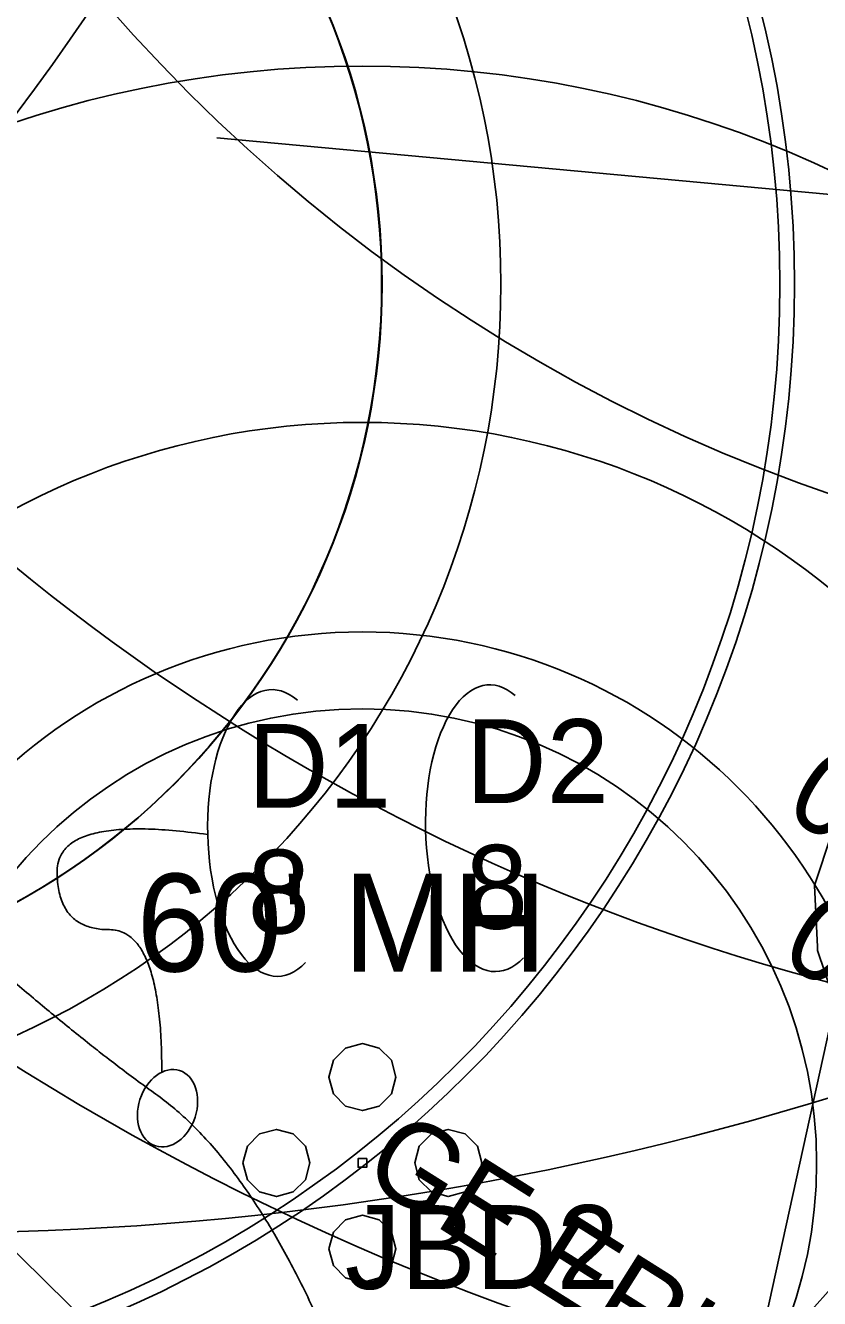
# Model space of a CAD drawing. Extents: x 1638506 to 1658005, y 834807 to 846788.
# Drawn here: x 1641345.7 to 1641459.3, y 842127.5 to 842309.7 of the extents above; entities that cross this region are included whole.
import ezdxf

# ---------------------------------------------------------------- set-up
doc = ezdxf.new("R2010")
doc.units = 0
for name, color, linetype in [('Default', 7, 'Continuous'), ('Old_Level_1', 7, 'Continuous'), ('Old_Level_2', 7, 'Continuous'), ('Old_Level_4', 7, 'Continuous'), ('Scratch_Level_0', 7, 'Continuous'), ('Sheet North Arrow CELL', 7, 'Continuous')]:
    doc.layers.add(name, color=color, linetype=linetype)

msp = doc.modelspace()

# ---------------------------------------------------------------- linework, layer by layer
at = {"layer": 'Default'}
msp.add_line((1641192.01, 842284.15), (1641394.9, 842084.34), dxfattribs=at)
for centre, start_param, end_param in [((1641412.54, 842194.83), 5.884886, 7.853982), ((1641381.36, 842194.15), 5.884886, 7.853982), ((1641412.54, 842194.83), 1.570796, 3.572354), ((1641381.36, 842194.15), 1.570796, 3.572354)]:
    msp.add_ellipse(centre, major_axis=(-0.49, 20.52), ratio=0.466223, start_param=start_param, end_param=end_param, dxfattribs=at)
msp.add_ellipse((1641366.05, 842154.75), major_axis=(-1.72, -5.4), ratio=0.730797, dxfattribs=at)
for points in [[(1641295.68, 842243.6), (1641303.97, 842209.15), (1641349.49, 842167.37), (1641379.28, 842146.14), (1641391.33, 842115.76)], [(1641365.23, 842159.91), (1641365.23, 842180.31), (1641350.25, 842180.31), (1641350.25, 842196.94), (1641371.79, 842193.93)]]:
    msp.add_open_spline(points, degree=2, dxfattribs=at)
at = {"layer": 'Old_Level_1'}
for radius in [365, 307, 240, 158, 101]:
    msp.add_circle((1641295.68, 842272.71), radius, dxfattribs=at)
at = {"layer": 'Old_Level_2'}
msp.add_line((1641373.11, 842293.63), (1642246.71, 842213.27), dxfattribs=at)
msp.add_arc((1641332.1, 842574.94), 438, 252.1948, 287.7872, dxfattribs=at)
at = {"layer": 'Old_Level_4'}
for points in [[(1641389.77, 842156.82), (1641391.52, 842155.06), (1641393.92, 842154.42), (1641396.32, 842155.06), (1641398.08, 842156.82), (1641398.72, 842159.22), (1641398.08, 842161.61), (1641396.32, 842163.37), (1641393.92, 842164.01), (1641391.52, 842163.37), (1641389.77, 842161.61), (1641389.12, 842159.22)], [(1641389.77, 842156.82), (1641391.52, 842155.06), (1641393.92, 842154.42), (1641396.32, 842155.06), (1641398.08, 842156.82), (1641398.72, 842159.22), (1641398.08, 842161.61), (1641396.32, 842163.37), (1641393.92, 842164.01), (1641391.52, 842163.37), (1641389.77, 842161.61), (1641389.12, 842159.22)], [(1641393.92, 842164.01), (1641391.52, 842163.37), (1641391.52, 842163.37)], [(1641396.32, 842163.37), (1641393.92, 842164.01), (1641393.92, 842164.01)], [(1641389.77, 842161.61), (1641389.12, 842159.22), (1641389.12, 842159.22)], [(1641391.52, 842163.37), (1641389.77, 842161.61), (1641389.77, 842161.61)], [(1641398.08, 842161.61), (1641396.32, 842163.37), (1641396.32, 842163.37)], [(1641398.72, 842159.22), (1641398.08, 842161.61), (1641398.08, 842161.61)], [(1641389.12, 842159.22), (1641389.77, 842156.82), (1641389.77, 842156.82)], [(1641398.08, 842156.82), (1641398.72, 842159.22), (1641398.72, 842159.22)], [(1641389.77, 842156.82), (1641391.52, 842155.06), (1641391.52, 842155.06)], [(1641396.32, 842155.06), (1641398.08, 842156.82), (1641398.08, 842156.82)], [(1641391.52, 842155.06), (1641393.92, 842154.42), (1641393.92, 842154.42)], [(1641393.92, 842154.42), (1641396.32, 842155.06), (1641396.32, 842155.06)], [(1641384.02, 842142.76), (1641385.78, 842144.51), (1641386.42, 842146.92), (1641385.78, 842149.32), (1641384.02, 842151.07), (1641381.62, 842151.72), (1641379.22, 842151.07), (1641377.47, 842149.32), (1641376.82, 842146.92), (1641377.47, 842144.51), (1641379.22, 842142.76), (1641381.62, 842142.11)], [(1641384.02, 842142.76), (1641385.78, 842144.51), (1641386.42, 842146.92), (1641385.78, 842149.32), (1641384.02, 842151.07), (1641381.62, 842151.72), (1641379.22, 842151.07), (1641377.47, 842149.32), (1641376.82, 842146.92), (1641377.47, 842144.51), (1641379.22, 842142.76), (1641381.62, 842142.11)], [(1641379.22, 842151.07), (1641377.47, 842149.32), (1641377.47, 842149.32)], [(1641381.62, 842151.72), (1641379.22, 842151.07), (1641379.22, 842151.07)], [(1641384.02, 842151.07), (1641381.62, 842151.72), (1641381.62, 842151.72)], [(1641385.78, 842149.32), (1641384.02, 842151.07), (1641384.02, 842151.07)], [(1641403.82, 842151.07), (1641402.07, 842149.32), (1641401.42, 842146.92), (1641402.07, 842144.51), (1641403.82, 842142.76), (1641406.22, 842142.11), (1641408.62, 842142.76), (1641410.38, 842144.51), (1641411.02, 842146.92), (1641410.38, 842149.32), (1641408.62, 842151.07), (1641406.22, 842151.72)], [(1641403.82, 842151.07), (1641402.07, 842149.32), (1641401.42, 842146.92), (1641402.07, 842144.51), (1641403.82, 842142.76), (1641406.22, 842142.11), (1641408.62, 842142.76), (1641410.38, 842144.51), (1641411.02, 842146.92), (1641410.38, 842149.32), (1641408.62, 842151.07), (1641406.22, 842151.72)], [(1641403.82, 842151.07), (1641402.07, 842149.32), (1641402.07, 842149.32)], [(1641406.22, 842151.72), (1641403.82, 842151.07), (1641403.82, 842151.07)], [(1641408.62, 842151.07), (1641406.22, 842151.72), (1641406.22, 842151.72)], [(1641410.38, 842149.32), (1641408.62, 842151.07), (1641408.62, 842151.07)], [(1641377.47, 842149.32), (1641376.82, 842146.92), (1641376.82, 842146.92)], [(1641386.42, 842146.92), (1641385.78, 842149.32), (1641385.78, 842149.32)], [(1641402.07, 842149.32), (1641401.42, 842146.92), (1641401.42, 842146.92)], [(1641411.02, 842146.92), (1641410.38, 842149.32), (1641410.38, 842149.32)], [(1641393.3, 842146.29), (1641394.55, 842146.29), (1641394.55, 842147.54), (1641393.3, 842147.54)], [(1641393.3, 842146.29), (1641394.55, 842146.29), (1641394.55, 842147.54), (1641393.3, 842147.54)], [(1641394.55, 842147.54), (1641393.3, 842147.54), (1641393.3, 842147.54), (1641394.55, 842147.54)], [(1641393.3, 842147.54), (1641393.3, 842146.29), (1641393.3, 842146.29), (1641393.3, 842147.54)], [(1641394.55, 842146.29), (1641394.55, 842147.54), (1641394.55, 842147.54), (1641394.55, 842146.29)], [(1641376.82, 842146.92), (1641377.47, 842144.51), (1641377.47, 842144.51)], [(1641385.78, 842144.51), (1641386.42, 842146.92), (1641386.42, 842146.92)], [(1641393.3, 842146.29), (1641394.55, 842146.29), (1641394.55, 842146.29), (1641393.3, 842146.29)], [(1641401.42, 842146.92), (1641402.07, 842144.51), (1641402.07, 842144.51)], [(1641410.38, 842144.51), (1641411.02, 842146.92), (1641411.02, 842146.92)], [(1641377.47, 842144.51), (1641379.22, 842142.76), (1641379.22, 842142.76)], [(1641384.02, 842142.76), (1641385.78, 842144.51), (1641385.78, 842144.51)], [(1641402.07, 842144.51), (1641403.82, 842142.76), (1641403.82, 842142.76)], [(1641408.62, 842142.76), (1641410.38, 842144.51), (1641410.38, 842144.51)], [(1641379.22, 842142.76), (1641381.62, 842142.11), (1641381.62, 842142.11)], [(1641381.62, 842142.11), (1641384.02, 842142.76), (1641384.02, 842142.76)], [(1641403.82, 842142.76), (1641406.22, 842142.11), (1641406.22, 842142.11)], [(1641406.22, 842142.11), (1641408.62, 842142.76), (1641408.62, 842142.76)], [(1641398.08, 842137.01), (1641396.32, 842138.77), (1641393.92, 842139.42), (1641391.52, 842138.77), (1641389.77, 842137.01), (1641389.12, 842134.61), (1641389.77, 842132.22), (1641391.52, 842130.46), (1641393.92, 842129.82), (1641396.32, 842130.46), (1641398.08, 842132.22), (1641398.72, 842134.61)], [(1641398.08, 842137.01), (1641396.32, 842138.77), (1641393.92, 842139.42), (1641391.52, 842138.77), (1641389.77, 842137.01), (1641389.12, 842134.61), (1641389.77, 842132.22), (1641391.52, 842130.46), (1641393.92, 842129.82), (1641396.32, 842130.46), (1641398.08, 842132.22), (1641398.72, 842134.61)], [(1641391.52, 842138.77), (1641389.77, 842137.01), (1641389.77, 842137.01)], [(1641393.92, 842139.42), (1641391.52, 842138.77), (1641391.52, 842138.77)], [(1641396.32, 842138.77), (1641393.92, 842139.42), (1641393.92, 842139.42)], [(1641398.08, 842137.01), (1641396.32, 842138.77), (1641396.32, 842138.77)], [(1641389.77, 842137.01), (1641389.12, 842134.61), (1641389.12, 842134.61)], [(1641398.72, 842134.61), (1641398.08, 842137.01), (1641398.08, 842137.01)], [(1641389.12, 842134.61), (1641389.77, 842132.22), (1641389.77, 842132.22)], [(1641398.08, 842132.22), (1641398.72, 842134.61), (1641398.72, 842134.61)], [(1641389.77, 842132.22), (1641391.52, 842130.46), (1641391.52, 842130.46)], [(1641396.32, 842130.46), (1641398.08, 842132.22), (1641398.08, 842132.22)], [(1641391.52, 842130.46), (1641393.92, 842129.82), (1641393.92, 842129.82)], [(1641393.92, 842129.82), (1641396.32, 842130.46), (1641396.32, 842130.46)]]:
    msp.add_lwpolyline(points, close=True, dxfattribs=at)
for centre, radius in [((1641051.91, 842515.45), 365), ((1641538.84, 842469.72), 365), ((1641051.91, 842515.45), 307), ((1641538.84, 842469.72), 307), ((1641538.84, 842469.72), 240), ((1641393.92, 842146.92), 219), ((1641393.92, 842146.92), 193), ((1641393.92, 842146.92), 157), ((1641393.92, 842146.92), 106), ((1641393.92, 842146.92), 76), ((1641393.92, 842146.92), 65)]:
    msp.add_circle(centre, radius, dxfattribs=at)
at = {"layer": 'Scratch_Level_0'}
msp.add_lwpolyline([(1641461.09, 842194.11), (1641458.63, 842186.63), (1641459.04, 842177.83), (1641459.06, 842177.31), (1641462.1, 842168.33)], dxfattribs=at)
for radius in [297, 264, 219, 160, 118, 101]:
    msp.add_circle((1641295.75, 842272.71), radius, dxfattribs=at)
at = {"layer": 'Sheet North Arrow CELL'}
msp.add_lwpolyline([(1641540.04, 842526.99), (1641447.29, 842104.99), (1641540.04, 842151.99)], close=True, dxfattribs=at)

# ---------------------------------------------------------------- texts
at = {"layer": 'Default'}
for s, p in [('D1', (1641377.51, 842197.75)), ('D2', (1641408.7, 842198.43)), ('8', (1641408.7, 842180.43)), ('8', (1641377.51, 842179.75)), ('JBD2', (1641391.42, 842128.88))]:
    msp.add_text(s, height=12, dxfattribs=at).set_placement(p)
at = {"layer": 'Old_Level_4'}
msp.add_text("60' MH", height=14, dxfattribs=at).set_placement((1641361.61, 842174.32))
at = {"layer": 'Scratch_Level_0'}
for s, p in [('0.1, 0.2, 0.4,', (1641453.92, 842197.02)), ('0.8, 1.0, 1.2', (1641453.29, 842176.16)), ('GE ERL2x23C340', (1641393.41, 842144.81))]:
    msp.add_text(s, height=12, rotation=327.8202, dxfattribs=at).set_placement(p)

doc.saveas('drawing.dxf')
